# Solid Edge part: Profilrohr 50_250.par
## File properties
Username: ahadarics
Dokumentum tartalom típus: 0
Author: ahadarics
Last saved by: ahadarics
Revision: 85
Sűrűség: 0,000 kg/m^3
Pontosság: 0,990
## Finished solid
Body 1: solid body, 175 faces, 519 edges, 346 vertices.
  Faces by surface: cylinder 107, plane 68
  Edges by curve: line 305, circle 214
Bounding box of the edges (mm): 60.200 x 60.200 x 294.000, from (-30.1, -30.1, -259.5) to (30.1, 30.1, 34.5).
Cylindrical faces by radius (mm): R0.1 x16, R0.2 x30, R0.5 x28, R1 x8, R3.75 x8, R5 x4, R6 x4, R25 x1, R27 x8
Planar faces by outward normal: +x 6, +y 6, +z 1, -x 4, -y 4, -z 1, oblique 46
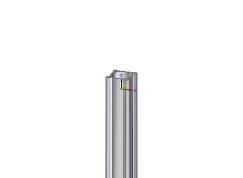
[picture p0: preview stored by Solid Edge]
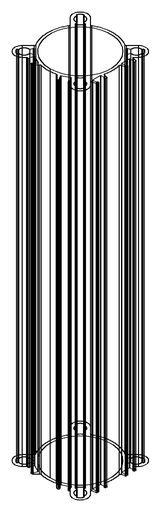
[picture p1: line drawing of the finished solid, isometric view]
